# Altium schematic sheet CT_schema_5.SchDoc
size 283 x 147 mm
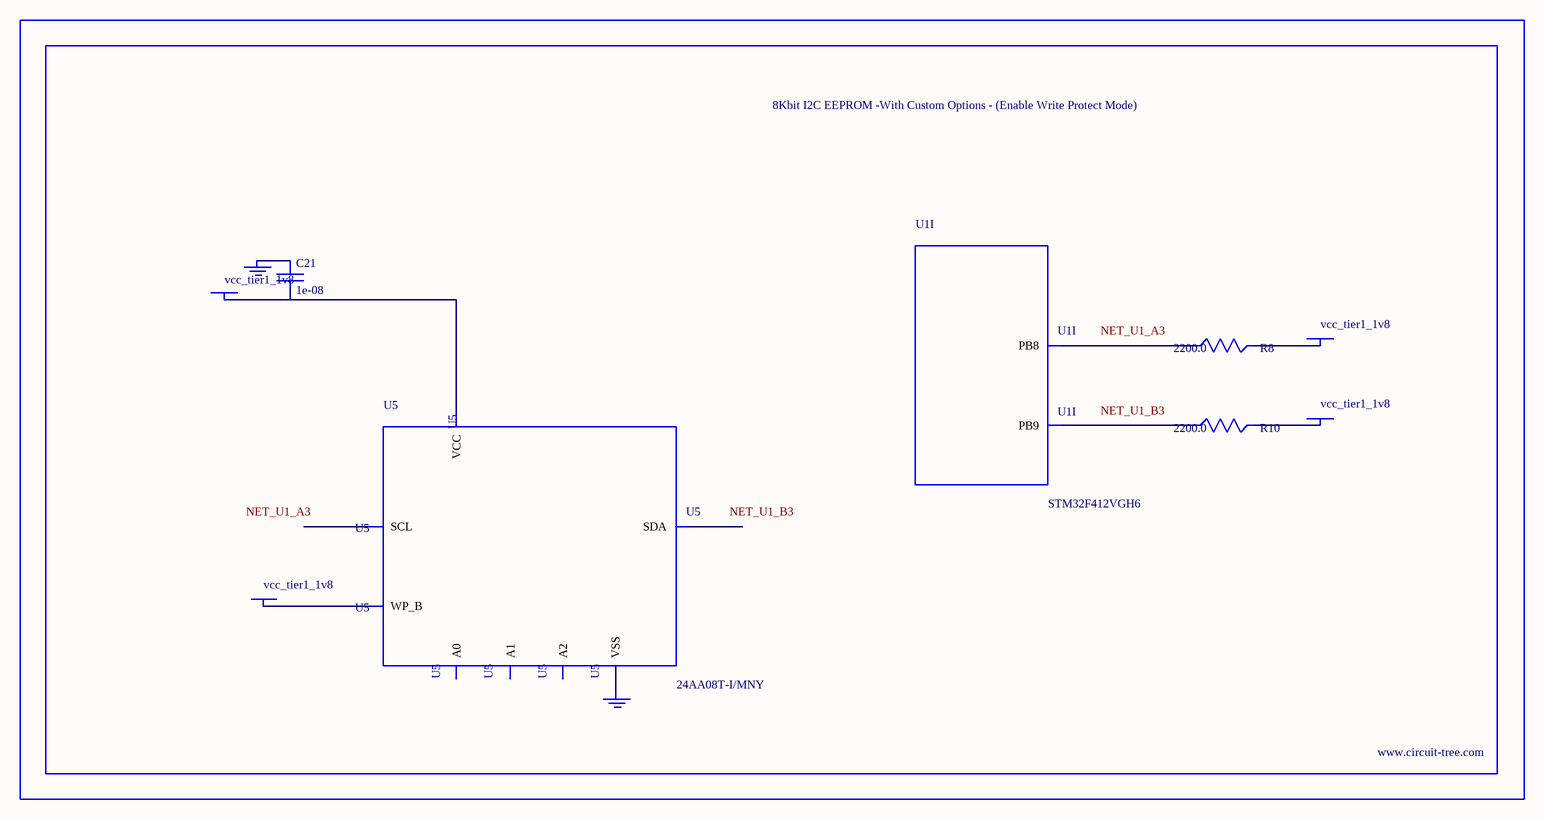
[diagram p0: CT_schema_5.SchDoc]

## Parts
BORDER4  (no value)
C21  1e-08  [C0402]
GND_INSTANCE_4_0  (no value)
GND_INSTANCE_4_1  (no value)
POWER_INSTANCE_4_0  vcc_tier1_1v8
POWER_INSTANCE_4_1  vcc_tier1_1v8
POWER_INSTANCE_4_2  vcc_tier1_1v8
POWER_INSTANCE_4_3  vcc_tier1_1v8
R8  2200.0  [R0603]
R10  2200.0  [R0603]
U1  STM32F412VGH6  [UFBGA100]  (part I of 11)
U5  24AA08T-I/MNY  [TDFN-8/6MM]

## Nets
NetC21_1: C21.1 GND_INSTANCE_4_0.0(GND)
NetC21_2: C21.2 POWER_INSTANCE_4_1.0(PWR) U5.8(VCC)
NetGND_INSTANCE_4_1_0: GND_INSTANCE_4_1.0(GND) U5.4(VSS)
NetPOWER_INSTANCE_4_0_0: POWER_INSTANCE_4_0.0(PWR) U5.7(WP_B)
NetPOWER_INSTANCE_4_2_0: POWER_INSTANCE_4_2.0(PWR) R8.2
NetPOWER_INSTANCE_4_3_0: POWER_INSTANCE_4_3.0(PWR) R10.2
NetR8_1: R8.1 U1.A3(PB8)
NetR10_1: R10.1 U1.B3(PB9)

Not connected (* = marked no-connect by the designer): U5 1(A0) 2(A1) 3(A2) 5(SDA) 6(SCL)

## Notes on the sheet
- Labels drawn without touching a wire or pin: NET_U1_A3, NET_U1_B3

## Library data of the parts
BORDER4 = BORDER_PAGE4
C21 = C0402C103K3RAC
GND_INSTANCE_4_0 GND_INSTANCE_4_1 = GND
POWER_INSTANCE_4_0-POWER_INSTANCE_4_3 = PWR
R8 R10 = RC0603JR-072K2L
